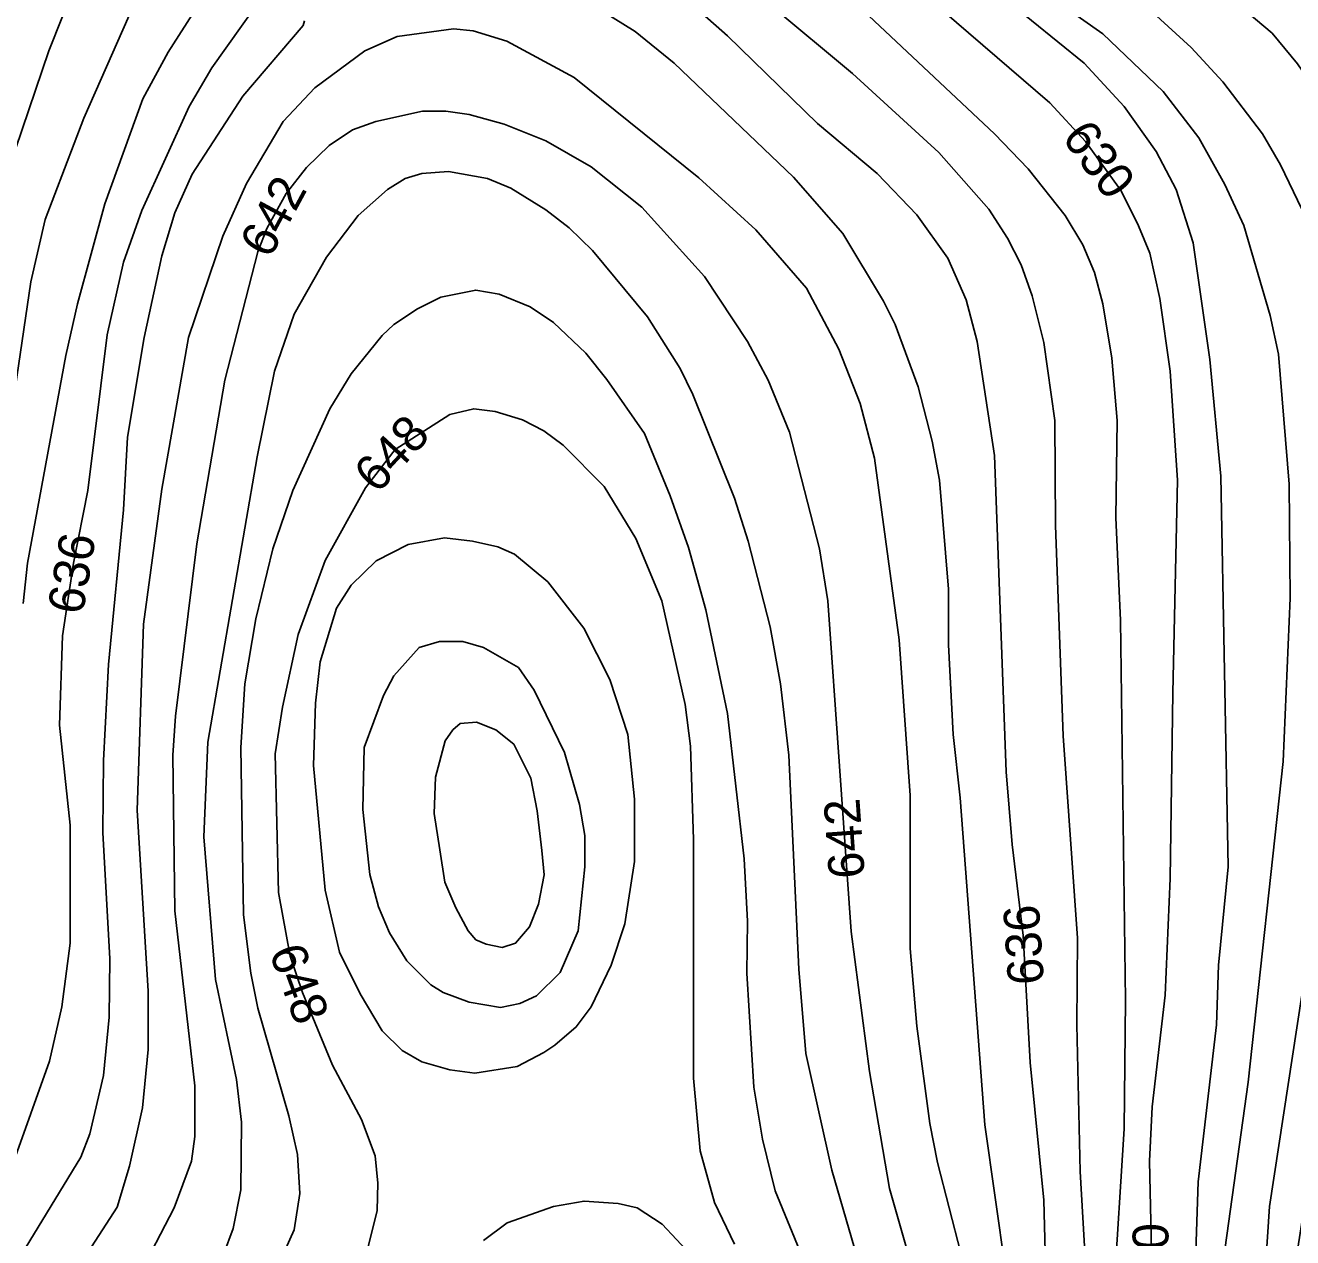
# Model space of a CAD drawing. Extents: x -709418 to -703832, y -1161719 to -1157826.
# Drawn here: x -708183.3 to -707900.7, y -1159896.5 to -1159626.2 of the extents above; entities that cross this region are included whole.
import ezdxf

# ---------------------------------------------------------------- set-up
doc = ezdxf.new("R2010")
doc.units = 0
for name, color, linetype in [('120_vrstevnice hlavní', 7, 'Continuous'), ('121_vrstevnice hlavní_popis', 7, 'Continuous'), ('122_vrstevnice základní', 7, 'Continuous'), ('124_vrstevnice doplňková', 7, 'Continuous')]:
    doc.layers.add(name, color=color, linetype=linetype)

msp = doc.modelspace()

# ---------------------------------------------------------------- linework, layer by layer
at = {"layer": '120_vrstevnice hlavní'}
for points in [[(-708189.46, -1159518.71), (-708173.4, -1159533.03), (-708165.73, -1159541.57), (-708161.39, -1159549.09), (-708158.79, -1159556.61), (-708157.92, -1159567.89), (-708159.37, -1159579.18), (-708163.13, -1159594.22), (-708178.03, -1159631.82)], [(-707927.94, -1159703.28), (-707930.25, -1159687.08), (-707932.52, -1159676.93), (-707935.03, -1159670.88), (-707938.93, -1159663.07), (-707946.89, -1159652.07), (-707954.84, -1159643.4), (-707993.75, -1159609.84)], [(-708173.43, -1159906.12), (-708162.84, -1159889.73), (-708160.09, -1159880.61), (-708157.2, -1159867.6), (-708155.9, -1159854.58), (-708155.9, -1159841.56), (-708158.36, -1159801.2), (-708156.91, -1159759.69), (-708152.86, -1159729.6), (-708146.93, -1159695.76), (-708139.26, -1159673.19), (-708133.97, -1159661.41), (-708125.81, -1159647.59), (-708118.72, -1159640.07), (-708107.59, -1159631.82), (-708100.35, -1159628.64), (-708087.77, -1159626.91), (-708083.43, -1159627.34), (-708075.91, -1159629.66), (-708060.87, -1159637.76), (-708033.1, -1159660.18), (-708020.37, -1159671.75), (-708009.08, -1159684.77), (-708001.85, -1159698.36), (-707997.08, -1159710.51), (-707993.9, -1159722.66), (-707988.4, -1159763.16), (-707985.94, -1159797.88), (-707985.94, -1159832.01), (-707984.49, -1159849.37), (-707981.6, -1159871.07), (-707979.86, -1159879.75), (-707972.06, -1159910.12)], [(-708178.03, -1159631.82), (-708187, -1159658.15)], [(-707931.7, -1159919.96), (-707932.57, -1159879.46), (-707931.99, -1159867.31), (-707929.1, -1159842.43), (-707927.94, -1159816.39), (-707927.36, -1159775.02), (-707926.35, -1159727.58), (-707927.94, -1159703.28)], [(-708077.94, -1159742.48), (-708074.17, -1159744.07), (-708066.79, -1159750.28), (-708058.73, -1159760.56), (-708052.93, -1159772.06), (-708048.9, -1159784.29), (-708047.42, -1159798.75), (-708047.42, -1159812.63), (-708049.58, -1159826.52), (-708052.62, -1159835.77), (-708057.1, -1159845.03), (-708060.43, -1159849.52), (-708065.21, -1159853.56), (-708067.68, -1159855.23), (-708073.6, -1159858.34), (-708083.02, -1159859.84), (-708088.64, -1159859.06), (-708094.86, -1159857.32), (-708099.24, -1159854.81), (-708103.68, -1159850.38), (-708108.6, -1159842.14), (-708113.23, -1159832.88), (-708116.41, -1159819), (-708119.01, -1159791.22), (-708118.58, -1159777.34), (-708117.57, -1159768.08), (-708113.89, -1159756.11), (-708110.61, -1159750.98), (-708105.07, -1159745.59), (-708097.9, -1159741.9), (-708089.8, -1159740.45), (-708083.58, -1159741.18), (-708077.94, -1159742.48)], [(-708081.12, -1159897.15), (-708075.83, -1159893.24), (-708065.48, -1159889.6), (-708058.68, -1159888.38), (-708051.11, -1159888.87), (-708046.83, -1159889.85), (-708041.28, -1159893.52), (-708031.65, -1159903.76)]]:
    msp.add_lwpolyline(points, dxfattribs=at)
at = {"layer": '122_vrstevnice základní'}
for points in [[(-708187.14, -1159717.74), (-708182.08, -1159683.32), (-708178.9, -1159669.43), (-708170.22, -1159646.87), (-708156.48, -1159615.62), (-708148.38, -1159600), (-708142.45, -1159586.12), (-708139.7, -1159577.44), (-708137.53, -1159568.18), (-708136.23, -1159556.03), (-708137.24, -1159545.91), (-708139.26, -1159539.83), (-708142.73, -1159533.76), (-708146.06, -1159529.71), (-708154.16, -1159522.18), (-708159.66, -1159517.99), (-708173.69, -1159509.6), (-708185.26, -1159501.65)], [(-708183.81, -1159755.06), (-708182.8, -1159746.09), (-708174.27, -1159699.81), (-708171.66, -1159688.24), (-708165.59, -1159665.96), (-708157.06, -1159642.53), (-708151.41, -1159632.11), (-708114.82, -1159574.83)], [(-707993.32, -1159659.16), (-708006.62, -1159648.03), (-708026.73, -1159628.5), (-708072.58, -1159588)], [(-708067.52, -1159614.9), (-708047.27, -1159627.49), (-708038.59, -1159634.57), (-708011.98, -1159660.03), (-708000.98, -1159672.61), (-707991.87, -1159687.66), (-707989.27, -1159692.86), (-707984.21, -1159706.75), (-707981.02, -1159718.9), (-707979.43, -1159727.58), (-707977.41, -1159751.88), (-707977.41, -1159764.32), (-707976.39, -1159784.28), (-707974.8, -1159798.46), (-707969.31, -1159871.36), (-707964.68, -1159903.76)], [(-707919.11, -1159700.68), (-707922.88, -1159674.64), (-707926.64, -1159662.78), (-707931.12, -1159654.25), (-707938.21, -1159644.26), (-707947.18, -1159634.57), (-707970.61, -1159615.48)], [(-708001.27, -1159618.23), (-707967.14, -1159650.34), (-707959.61, -1159658.15), (-707951.37, -1159668.56), (-707947.42, -1159675.11), (-707944.86, -1159681.29), (-707942.98, -1159688.24), (-707940.96, -1159700.39), (-707939.8, -1159714.27), (-707940.09, -1159735.97), (-707939.08, -1159758.82), (-707937.92, -1159843.58), (-707938.21, -1159872.22), (-707940.52, -1159908.68)], [(-707900.6, -1159906.07), (-707893.66, -1159860.94), (-707882.38, -1159806.27), (-707880.35, -1159788.04), (-707877.02, -1159767.5), (-707873.12, -1159734.23), (-707873.7, -1159715.72), (-707877.75, -1159687.95), (-707881.8, -1159671.75), (-707887.15, -1159655.55), (-707893.22, -1159643.98), (-707899.59, -1159634.72), (-707905.23, -1159627.92), (-707916.8, -1159618.08)], [(-708131.6, -1159621.41), (-708141.72, -1159635.59), (-708146.79, -1159644.27), (-708157.34, -1159667.41), (-708161.39, -1159678.98), (-708165.01, -1159695.18), (-708169.35, -1159729.89), (-708172.53, -1159746.09), (-708174.99, -1159762.29), (-708175.71, -1159782.26), (-708173.26, -1159804.53), (-708173.26, -1159830.86), (-708175.14, -1159845.03), (-708177.88, -1159857.18), (-708185.84, -1159879.46)], [(-708017.04, -1159621.7), (-707998.81, -1159636.89), (-707979.58, -1159654.53), (-707968.44, -1159667.12), (-707964.24, -1159673.63), (-707961.21, -1159679.56), (-707958.75, -1159686.5), (-707956.14, -1159696.92), (-707953.69, -1159714.27), (-707953.54, -1159737.71), (-707951.8, -1159784.57), (-707948.62, -1159829.7), (-707948.77, -1159849.08), (-707948.04, -1159881.77), (-707946.31, -1159911.28)], [(-707916.51, -1159904.62), (-707910.58, -1159861.81), (-707902.77, -1159790.35), (-707901.18, -1159753.91), (-707901.47, -1159728.45), (-707903.78, -1159699.52), (-707905.66, -1159690.84), (-707911.57, -1159670.82), (-707915.79, -1159661.62), (-707921.57, -1159651.21), (-707929.53, -1159640.94), (-707942.98, -1159628.06), (-707952.24, -1159621.56)], [(-707933.58, -1159621.7), (-707923.31, -1159631.1), (-707916.22, -1159638.77), (-707907.4, -1159650.34), (-707903.35, -1159657.28), (-707896.7, -1159671.17), (-707893.37, -1159680.43), (-707890.91, -1159689.68), (-707888.16, -1159703.57), (-707886.86, -1159717.46), (-707886.86, -1159729.03), (-707892.5, -1159796.14), (-707896.55, -1159828.83), (-707905.81, -1159889.58), (-707907.83, -1159919.96)], [(-708190.03, -1159909.83), (-708170.94, -1159878.59), (-708168.92, -1159873.38), (-708165.88, -1159860.36), (-708164.58, -1159847.34), (-708164.43, -1159834.33), (-708166.02, -1159806.14), (-708165.88, -1159790.07), (-708164.72, -1159768.66), (-708161.39, -1159734.23), (-708160.53, -1159718.03), (-708156.77, -1159695.76), (-708152.86, -1159677.53), (-708149.97, -1159667.99), (-708146.06, -1159659.31), (-708134.78, -1159641.95), (-708121.33, -1159626.18), (-708121.04, -1159625.17)], [(-707999.1, -1159828.25), (-708004.31, -1159754.48), (-708006.19, -1159742.91), (-708012.84, -1159716.88), (-708017.62, -1159705.3), (-708022.25, -1159696.63), (-708031.79, -1159682.16), (-708045.82, -1159666.68), (-708057.11, -1159657.72), (-708067.23, -1159651.93), (-708076.49, -1159648.17), (-708084.3, -1159646), (-708089.51, -1159645.28), (-708094.71, -1159645.28), (-708105.13, -1159647.59), (-708110.34, -1159649.47), (-708115.54, -1159652.94), (-708120.6, -1159657.86), (-708125.09, -1159663.65), (-708129.43, -1159671.46), (-708131.45, -1159676.67), (-708138.83, -1159705.3), (-708145.05, -1159741.76), (-708149.82, -1159780.23), (-708150.4, -1159788.91), (-708149.97, -1159823.62), (-708145.48, -1159862.68), (-708145.48, -1159873.96), (-708146.21, -1159879.46), (-708150.11, -1159889.87), (-708158.21, -1159905.49)], [(-708123.35, -1159690.55), (-708116.12, -1159677.82), (-708109.03, -1159668.56), (-708102.52, -1159662.78), (-708098.62, -1159660.32), (-708094.86, -1159659.16), (-708088.93, -1159658.73), (-708080.25, -1159660.32), (-708075.04, -1159662.49), (-708067.23, -1159667.26), (-708062.02, -1159671.31), (-708056.82, -1159676.38), (-708044.52, -1159691.13), (-708037.29, -1159702.7), (-708034.4, -1159708.49), (-708025.14, -1159731.63), (-708022.1, -1159741.18), (-708017.18, -1159760.27), (-708014.87, -1159773), (-708012.99, -1159788.91), (-708010.82, -1159836.64), (-708009.23, -1159855.45), (-708003.44, -1159881.48), (-707998.38, -1159898.84)], [(-707955.85, -1159899.71), (-707956.14, -1159888.14), (-707959.18, -1159857.47), (-707960.77, -1159829.12), (-707963.23, -1159808.87), (-707964.53, -1159792.67), (-707967.14, -1159722.08), (-707971.04, -1159696.63), (-707973.5, -1159687.37), (-707977.55, -1159678.11), (-707984.49, -1159668.42), (-707993.32, -1159659.16)], [(-707987.53, -1159955.54), (-708016.03, -1159886.11), (-708018.92, -1159874.54), (-708020.8, -1159862.97), (-708022.39, -1159837.51), (-708022.25, -1159825.94), (-708022.97, -1159812.05), (-708026.73, -1159779.65), (-708031.5, -1159756.51), (-708035.41, -1159742.62), (-708039.46, -1159731.05), (-708045.24, -1159717.17), (-708053.63, -1159705.16), (-708058.26, -1159699.23), (-708065.49, -1159692.43), (-708070.7, -1159688.96), (-708077.65, -1159686.07), (-708082.85, -1159685.2), (-708090.66, -1159686.79), (-708095.87, -1159689.39), (-708101.08, -1159692.86), (-708103.68, -1159695.32), (-708110.62, -1159703.86), (-708115.4, -1159711.67), (-708123.64, -1159729.89), (-708128.13, -1159742.91), (-708131.89, -1159758.53), (-708134.35, -1159773), (-708135.21, -1159787.17), (-708134.64, -1159824.49), (-708133.04, -1159837.51), (-708131.45, -1159845.32), (-708124.51, -1159869.33), (-708122.63, -1159878.01), (-708122.05, -1159886.69), (-708123.35, -1159894.79), (-708130.3, -1159910.41)], [(-708205.37, -1160024.68), (-708181.21, -1159970.58), (-708168.63, -1159946.57), (-708146.21, -1159914.75), (-708141.29, -1159906.07), (-708136.95, -1159894.5), (-708135.21, -1159885.82), (-708135.07, -1159870.78), (-708136.23, -1159861.23), (-708140.85, -1159838.96), (-708143.46, -1159807.13), (-708142.59, -1159786.02), (-708131.6, -1159722.37), (-708127.69, -1159703.28), (-708123.35, -1159690.55)], [(-707922.88, -1159917.35), (-707921.72, -1159884.08), (-707917.67, -1159849.08), (-707917.23, -1159835.77), (-707915.07, -1159813.79), (-707916.66, -1159726.71), (-707919.11, -1159700.68)], [(-708025.14, -1159897.97), (-708029.62, -1159888.71), (-708032.81, -1159877.14), (-708034.25, -1159860.94), (-708034.25, -1159807.71), (-708034.97, -1159786.88), (-708036.13, -1159777.63), (-708041.34, -1159754.48), (-708047.12, -1159740.6), (-708054.21, -1159729.03), (-708063.33, -1159719.77), (-708067.67, -1159716.59), (-708072.44, -1159714.13), (-708078.51, -1159712.25), (-708083.29, -1159711.67), (-708088.64, -1159712.97), (-708100.79, -1159720.78), (-708107.44, -1159729.31), (-708116.41, -1159745.52), (-708122.43, -1159762.02), (-708125.96, -1159778.21), (-708127.55, -1159788.62), (-708126.82, -1159819.57), (-708124.22, -1159833.75), (-708121.47, -1159841.85), (-708114.82, -1159858.05), (-708108.31, -1159870.2), (-708105.27, -1159878.3), (-708104.69, -1159884.37), (-708104.84, -1159890.45), (-708106.86, -1159898.55)], [(-708085.75, -1159763.6), (-708081.12, -1159764.9), (-708073.31, -1159769.38), (-708069.83, -1159774.45), (-708063.04, -1159788.33), (-708059.71, -1159799.9), (-708058.55, -1159806.84), (-708058.55, -1159813.79), (-708060, -1159828.11), (-708064.03, -1159837.4), (-708069.26, -1159842.57), (-708073.02, -1159844.31), (-708077.36, -1159845.18), (-708084.3, -1159844.02), (-708090.09, -1159841.85), (-708092.83, -1159840.11), (-708098.19, -1159834.76), (-708102.09, -1159828.54), (-708104.55, -1159822.76), (-708106.43, -1159815.52), (-708108.02, -1159801.06), (-708107.73, -1159787.17), (-708103.39, -1159775.6), (-708101.08, -1159771.26), (-708095.44, -1159764.9), (-708090.95, -1159763.6), (-708085.75, -1159763.6)], [(-707974.95, -1159940.21), (-707990.57, -1159885.53), (-707995.05, -1159859.5), (-707999.1, -1159828.25)]]:
    msp.add_lwpolyline(points, dxfattribs=at)
at = {"layer": '124_vrstevnice doplňková'}
msp.add_lwpolyline([(-708091.82, -1159793.83), (-708089.65, -1159785.73), (-708087.97, -1159783.3), (-708086.34, -1159781.84), (-708082.68, -1159781.59), (-708078.4, -1159783.3), (-708074.36, -1159786.48), (-708070.58, -1159794.06), (-708069.11, -1159801.35), (-708068.1, -1159810.17), (-708067.56, -1159815.64), (-708068.85, -1159822.16), (-708070.88, -1159827.19), (-708073.95, -1159830.82), (-708076.97, -1159831.8), (-708080.5, -1159831.06), (-708082.8, -1159830.08), (-708084.53, -1159828.13), (-708087.31, -1159822.99), (-708089.74, -1159817.24), (-708090.84, -1159810.03), (-708092.11, -1159801.93), (-708091.82, -1159793.83)], dxfattribs=at)

# ---------------------------------------------------------------- texts
at = {"layer": '121_vrstevnice hlavní_popis'}
for s, rotation, p in [('630', 306.3805, (-707952.32, -1159651.19)), ('642', 61.6935, (-708128.78, -1159678.45)), ('648', 47.1806, (-708104.79, -1159730.84)), ('636', 80.4652, (-708170.5, -1159757.8)), ('642', 93.9635, (-707996.05, -1159816.16)), ('636', 93.7782, (-707956.09, -1159839.87)), ('648', 290.1678, (-708129.01, -1159832.82)), ('630', 91.2257, (-707928.04, -1159911.02))]:
    msp.add_text(s, height=8, rotation=rotation, dxfattribs=at).set_placement(p)

doc.saveas('drawing.dxf')
